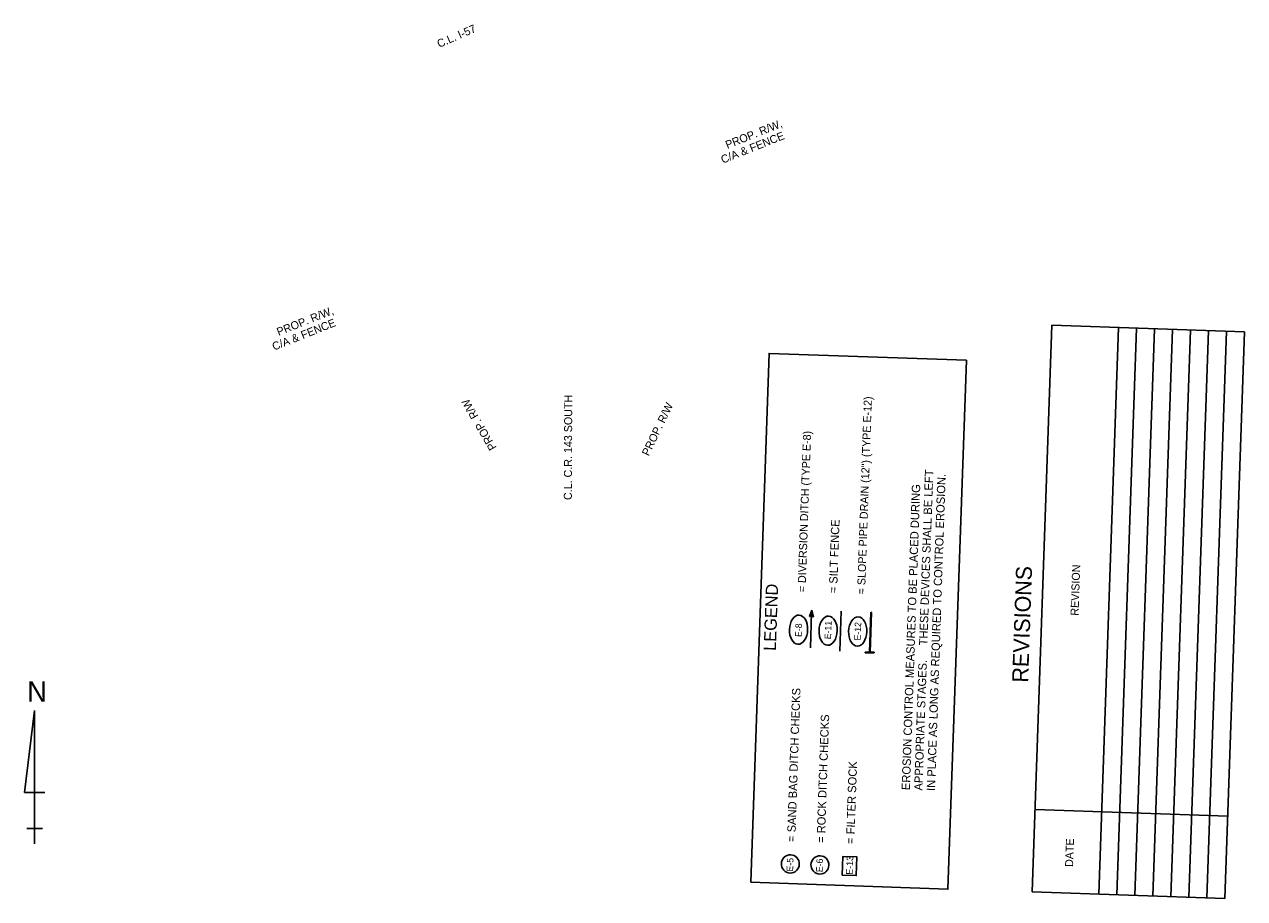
# Model space of a CAD drawing. Extents: x 1722483 to 1723478, y 767962 to 769496.
# Drawn here: x 1722516 to 1723431, y 767962 to 768617 of the extents above; entities that cross this region are included whole.
import ezdxf

# ---------------------------------------------------------------- set-up
doc = ezdxf.new("R2010")
doc.units = 0
for name, color, linetype in [('Default', 7, 'Continuous'), ('Level 1', 7, 'Continuous'), ('Level 44', 7, 'Continuous'), ('R_Border Prem', 7, 'Continuous'), ('R_Draft', 7, 'Continuous'), ('R_No Plot', 7, 'Continuous')]:
    doc.layers.add(name, color=color, linetype=linetype)

msp = doc.modelspace()

# ---------------------------------------------------------------- linework, layer by layer
at = {"layer": 'Default'}
for p, q in [((1723271.29, 767967.16), (1723286.12, 768391.9)), ((1723286.12, 768391.9), (1723430.53, 768386.86)), ((1723321.26, 767965.42), (1723336.09, 768390.16)), ((1723334.75, 767964.95), (1723349.58, 768389.69)), ((1723348.24, 767964.48), (1723363.07, 768389.22)), ((1723361.73, 767964.01), (1723376.57, 768388.75)), ((1723361.73, 767964.01), (1723376.57, 768388.75)), ((1723375.23, 767963.54), (1723390.06, 768388.28)), ((1723388.72, 767963.06), (1723403.55, 768387.81)), ((1723402.21, 767962.59), (1723417.04, 768387.33)), ((1723415.7, 767962.12), (1723430.53, 768386.86)), ((1723273.45, 768028.94), (1723417.86, 768023.89)), ((1723271.29, 767967.16), (1723415.7, 767962.12))]:
    msp.add_line(p, q, dxfattribs=at)
at = {"layer": 'Level 1'}
for p, q in [((1723106.07, 768178.28), (1723104.46, 768173.53)), ((1723104.46, 768173.53), (1723107.34, 768173.43)), ((1723105.74, 768177.05), (1723104.82, 768173.53)), ((1723105.83, 768177.03), (1723105.18, 768173.51)), ((1723105.93, 768177.01), (1723105.53, 768173.51)), ((1723107.34, 768173.43), (1723106.07, 768178.28)), ((1723106.26, 768173.47), (1723106.12, 768177.01)), ((1723106.62, 768173.46), (1723106.21, 768177.01)), ((1723106.98, 768173.45), (1723106.3, 768177.03))]:
    msp.add_line(p, q, dxfattribs=at)
msp.add_lwpolyline([(1723105.08, 768150.11), (1723106.01, 768176.6)], dxfattribs=at)
for centre, major_axis, ratio in [((1723096.22, 768163.68), (0.38, 10.95), 0.622952), ((1723118.39, 768162.93), (0.37, 10.95), 0.622952), ((1723140.58, 768162.28), (0.38, 10.95), 0.622952), ((1723090.09, 767988.1), (-0.23, -6.88), 0.97521), ((1723112.25, 767987.35), (-0.23, -6.88), 0.97521)]:
    msp.add_ellipse(centre, major_axis=major_axis, ratio=ratio, dxfattribs=at)
at = {"layer": 'Level 44'}
for p, q in [((1723150.41, 768176.69), (1723149.37, 768146.84)), ((1723150.91, 768176.67), (1723149.87, 768146.82)), ((1723150.41, 768176.69), (1723150.91, 768176.67)), ((1723146.24, 768146.44), (1723146.26, 768146.94)), ((1723152.96, 768146.21), (1723146.24, 768146.44)), ((1723149.37, 768146.84), (1723146.26, 768146.94)), ((1723152.98, 768146.71), (1723149.87, 768146.82)), ((1723152.96, 768146.21), (1723152.98, 768146.71))]:
    msp.add_line(p, q, dxfattribs=at)
msp.add_lwpolyline([(1723127.2, 768147.56), (1723128.21, 768177.67)], dxfattribs=at)
at = {"layer": 'R_Border Prem'}
for p, q in [((1722523.7, 768103.22), (1722516.01, 768041.68)), ((1722523.7, 768003.22), (1722523.7, 768103.22)), ((1722523.7, 768103.22), (1722523.7, 768026.3)), ((1722516.01, 768041.68), (1722531.39, 768041.68)), ((1722523.7, 768003.22), (1722523.7, 768026.3)), ((1722523.7, 768014.76), (1722517.93, 768014.76)), ((1722517.93, 768014.76), (1722529.47, 768014.76)), ((1722523.7, 768003.22), (1722523.7, 768014.76))]:
    msp.add_line(p, q, dxfattribs=at)
at = {"layer": 'R_No Plot'}
for points in [[(1723060.34, 767974.36), (1723074.19, 768370.77), (1723221.99, 768365.61), (1723208.14, 767969.19)], [(1723129, 767979.76), (1723129.49, 767993.78), (1723139.99, 767993.42), (1723139.5, 767979.4)]]:
    msp.add_lwpolyline(points, close=True, dxfattribs=at)

# ---------------------------------------------------------------- texts
at = {"layer": 'Default'}
for s, height, p in [('REVISIONS', 12, (1723268.26, 768123.87)), ('REVISION', 6, (1723306.03, 768174.06)), ('DATE', 6, (1723301.96, 767985.75))]:
    msp.add_text(s, height=height, rotation=88, dxfattribs=at).set_placement(p)
at = {"layer": 'Level 1'}
for s, height, rotation, p in [('= SLOPE PIPE DRAIN (12") (TYPE E-12)', 6, 88.00001, (1723146.05, 768190.09)), ('= DIVERSION DITCH (TYPE E-8)', 6, 88.00001, (1723101.45, 768191.65)), ('THESE DEVICES SHALL BE LEFT', 6.25, 88.058, (1723192.78, 768151.82)), ('IN PLACE AS LONG AS REQUIRED TO CONTROL EROSION.', 6.25, 88.058, (1723198.5, 768042.71)), ('EROSION CONTROL MEASURES TO BE PLACED DURING', 6.25, 88.058, (1723179.69, 768043.34)), ('= SILT FENCE', 6.25, 88.058, (1723125.12, 768190.83)), ('E-8', 4.876, 88.00001, (1723098.47, 768158.19)), ('E-11 ', 4.876, 88.058, (1723120.56, 768156.46)), ('E-12', 4.876, 88.00001, (1723142.75, 768155.54)), ('APPROPRIATE STAGES. ', 6.25, 88.058, (1723189.09, 768043.02)), ('= SAND BAG DITCH CHECKS', 6.25, 88.058, (1723093.78, 768004.51)), ('= ROCK DITCH CHECKS', 6.25, 88.058, (1723115.94, 768003.76)), ('= FILTER SOCK', 6.25, 88.00001, (1723137.98, 768002.99)), ('E-5 ', 4.876, 88.058, (1723092.12, 767982.39)), ('E-6 ', 4.876, 88.058, (1723114.2, 767981.86))]:
    msp.add_text(s, height=height, rotation=rotation, dxfattribs=at).set_placement(p)
at = {"layer": 'Level 44'}
msp.add_text('LEGEND', height=9.143, rotation=88.058, dxfattribs=at).set_placement((1723079.23, 768147.74))
at = {"layer": 'R_Border Prem'}
msp.add_text('N', height=15.38, rotation=360, dxfattribs=at).set_placement((1722518.07, 768109.63))
at = {"layer": 'R_Draft'}
for s, rotation, p in [('C.L. I-57', 23.58961, (1722826.93, 768599.71)), ('PROP. R/W,', 21.75145, (1723042.86, 768524)), ('C/A & FENCE', 21.75145, (1723039.48, 768512.96)), ('PROP. R/W,', 21.75145, (1722706.54, 768383.84)), ('C/A & FENCE', 21.75145, (1722703.16, 768372.8)), ('C.L. C.R. 143 SOUTH', 89.76966, (1722926.31, 768260.83)), ('PROP. R/W', 120.05332, (1722870.09, 768300.26)), ('PROP. R/W', 64.32039, (1722983.9, 768293.39))]:
    msp.add_text(s, height=6, rotation=rotation, dxfattribs=at).set_placement(p)
at = {"layer": 'R_No Plot'}
msp.add_text('E-13', height=4.999, rotation=87.61773, dxfattribs=at).set_placement((1723136.72, 767979.9))

doc.saveas('drawing.dxf')
